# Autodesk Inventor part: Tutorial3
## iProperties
Shininess: 64.0
Length Units: 11269
Angle Units: 11279
Time Units: 11290
Mass Units: 11283
Length Display Precision: 3
Angle Display Precision: 2
Compacted: True
Part Number: Tutorial3
Document SubType Name: Modeling
Created: 2002-11
Designer: deepak
Density: 0.0
Volumn: 0.0
Area: 0.0
PropertySet Name: Model Information
Control State: 0
Master: False
Checked Out: False
Author: deepak
